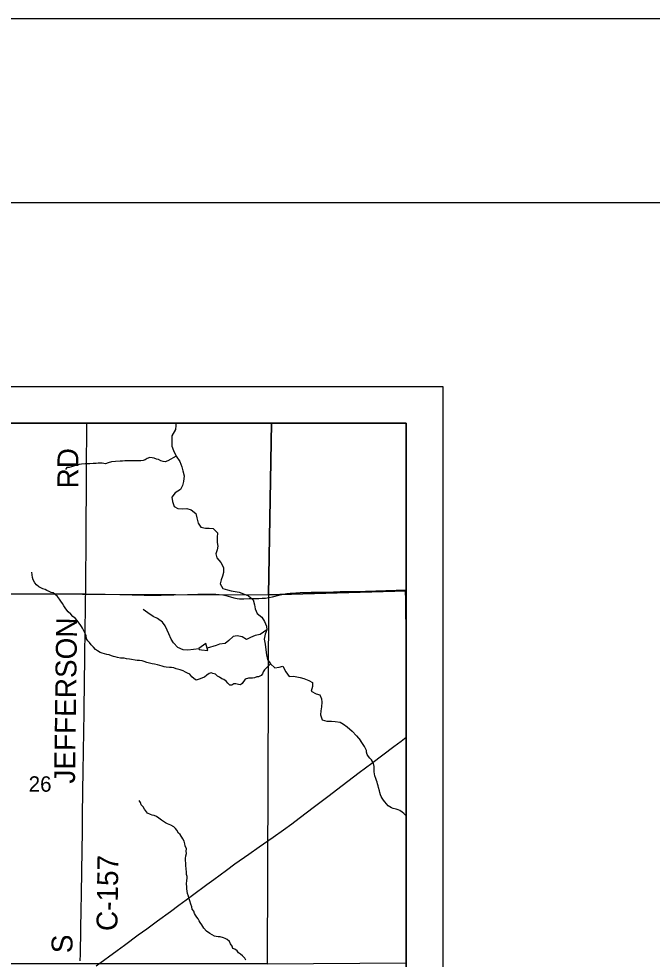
# Model space of a CAD drawing. Extents: x 0 to 34, y 0 to 22.
# Drawn here: x 7.847 to 9.569, y 19.442 to 22 of the extents above; entities that cross this region are included whole.
import ezdxf

# ---------------------------------------------------------------- set-up
doc = ezdxf.new("R2010")
doc.units = 0
for name, color, linetype in [('Default', 7, 'Continuous'), ('GM_X_County_Road', 7, 'Continuous'), ('GM_X_County_Road_Text', 7, 'Continuous'), ('GM_X_Minor_Lake', 7, 'Continuous'), ('GM_X_Minor_River', 7, 'Continuous'), ('GM_X_Section', 7, 'Continuous'), ('GM_X_Section_Text', 7, 'Continuous'), ('GM_X_State_Route', 7, 'Continuous'), ('GM_X_Township_Road', 7, 'Continuous'), ('SH_Border', 7, 'Continuous'), ('SH_Cut_Line', 7, 'Continuous'), ('SH_Data', 7, 'Continuous')]:
    doc.layers.add(name, color=color, linetype=linetype)

msp = doc.modelspace()

# ---------------------------------------------------------------- linework, layer by layer
at = {"layer": 'Default'}
msp.add_lwpolyline([(6.4755, 18.4174), (6.6827, 18.4182), (7.4947, 18.4149), (8.508, 18.4199), (8.7888, 18.4255), (8.8212, 18.4259), (8.9, 18.4271), (8.9, 20.9), (2.6032, 20.9)], dxfattribs=at)
for points in [[(8.5341, 20.9), (7.5179, 20.9), (7.5127, 20.4367), (8.5257, 20.4329)], [(8.9, 20.4436), (8.9, 20.9), (8.5341, 20.9), (8.5257, 20.4329)], [(8.9, 19.4325), (8.9, 20.4436), (8.5257, 20.4329), (8.5218, 19.4295)]]:
    msp.add_lwpolyline(points, close=True, dxfattribs=at)
at = {"layer": 'GM_X_County_Road'}
for points in [[(8.029, 20.4358), (8.0288, 20.4392), (8.029, 20.4609), (8.0294, 20.5044), (8.03, 20.5448), (8.03, 20.5635), (8.0302, 20.6132), (8.0304, 20.6505), (8.0307, 20.697), (8.0311, 20.7685), (8.0312, 20.7903), (8.0314, 20.8182), (8.0316, 20.8493), (8.032, 20.899), (8.0321, 20.9)], [(8.0142, 19.4373), (8.0145, 19.4559), (8.0151, 19.4817), (8.0153, 19.4974), (8.0156, 19.5104), (8.0159, 19.5212), (8.0159, 19.5283), (8.016, 19.5363), (8.016, 19.5444), (8.0162, 19.5564), (8.0165, 19.5698), (8.0169, 19.5912), (8.0171, 19.6037), (8.0174, 19.6254), (8.0182, 19.6751), (8.0192, 19.7435), (8.0197, 19.7839), (8.0204, 19.8304), (8.0214, 19.9019), (8.0223, 19.9516), (8.0232, 20.0075), (8.0237, 20.0603), (8.0245, 20.1131), (8.0256, 20.2032), (8.0262, 20.2529), (8.0265, 20.2685), (8.0268, 20.2933), (8.0271, 20.3119), (8.0275, 20.3492), (8.0281, 20.3865), (8.0284, 20.4051), (8.0287, 20.4268), (8.029, 20.4358)]]:
    msp.add_lwpolyline(points, dxfattribs=at)
at = {"layer": 'GM_X_Minor_Lake'}
for points in [[(8.3555, 20.3004), (8.3367, 20.2874), (8.3378, 20.2844), (8.3439, 20.2833), (8.3613, 20.2819)], [(8.3613, 20.2819), (8.3555, 20.3004)]]:
    msp.add_lwpolyline(points, dxfattribs=at)
at = {"layer": 'GM_X_Minor_River'}
for points in [[(8.2735, 20.9), (8.2742, 20.8939), (8.2728, 20.8829), (8.263, 20.8658), (8.2627, 20.8521), (8.2632, 20.8374), (8.2674, 20.8256), (8.2751, 20.8105), (8.2846, 20.7958), (8.2904, 20.781), (8.2931, 20.7708), (8.2962, 20.7568), (8.2952, 20.7416)], [(8.2751, 20.8105), (8.2519, 20.7972), (8.2451, 20.7953), (8.2391, 20.796), (8.233, 20.7979), (8.2265, 20.8009), (8.2216, 20.802), (8.2151, 20.8047), (8.2098, 20.8062), (8.2033, 20.8069), (8.1961, 20.8038), (8.1901, 20.8), (8.1848, 20.7985), (8.1791, 20.798), (8.1658, 20.7976), (8.1582, 20.7976), (8.1533, 20.7975), (8.1468, 20.7979), (8.1415, 20.7979), (8.1351, 20.7975), (8.1286, 20.7967), (8.1222, 20.7963), (8.11, 20.7958), (8.0994, 20.795), (8.0903, 20.7919), (8.0827, 20.7896), (8.074, 20.7911), (8.063, 20.7911), (8.0569, 20.7906), (8.0493, 20.7902), (8.0398, 20.7894), (8.0277, 20.7894), (8.0175, 20.7886), (8.0114, 20.7874), (8.0065, 20.7862), (8.0008, 20.7851), (7.9955, 20.7831), (7.9898, 20.7812), (7.9841, 20.7797), (7.978, 20.7793), (7.9743, 20.7739)], [(8.2952, 20.7416), (8.2918, 20.7302), (8.2862, 20.7199), (8.2722, 20.7103), (8.2628, 20.6985), (8.2644, 20.6868), (8.2698, 20.6735), (8.2793, 20.6679), (8.2918, 20.6672), (8.3039, 20.6684), (8.3153, 20.6647), (8.3282, 20.6542), (8.3313, 20.6424), (8.3344, 20.628), (8.342, 20.6171), (8.3546, 20.6145), (8.3648, 20.6149), (8.375, 20.6138), (8.3872, 20.6014), (8.3865, 20.5893), (8.3866, 20.5752), (8.3882, 20.5654), (8.3859, 20.5555), (8.3826, 20.5445), (8.3853, 20.5339), (8.396, 20.5214), (8.4036, 20.5078), (8.4033, 20.4938), (8.4007, 20.4839), (8.397, 20.4736), (8.394, 20.463), (8.402, 20.4505), (8.4146, 20.4464), (8.4248, 20.4442), (8.4354, 20.442), (8.4457, 20.4402), (8.4582, 20.4357), (8.4718, 20.4308), (8.484, 20.4199), (8.4879, 20.4055), (8.4898, 20.3949), (8.4948, 20.3828), (8.5081, 20.3726), (8.5154, 20.3609), (8.5208, 20.3477), (8.5212, 20.3378), (8.5171, 20.3264), (8.5142, 20.3127), (8.5165, 20.2991), (8.5189, 20.2836), (8.5201, 20.2703), (8.5232, 20.2574), (8.5312, 20.2453), (8.543, 20.2344), (8.5547, 20.2367), (8.5646, 20.2387), (8.573, 20.224), (8.5818, 20.2107), (8.5942, 20.2116), (8.6117, 20.2079), (8.6216, 20.2053), (8.6352, 20.2004), (8.6451, 20.1948), (8.6452, 20.1838), (8.6422, 20.1709), (8.6555, 20.1638), (8.6653, 20.1615), (8.6703, 20.1506), (8.6708, 20.1411), (8.6701, 20.1282), (8.6682, 20.1172), (8.6675, 20.1066), (8.6714, 20.0933), (8.6847, 20.0892), (8.6976, 20.0897), (8.707, 20.089), (8.7203, 20.0871), (8.7298, 20.0815), (8.7401, 20.0744), (8.7534, 20.0627), (8.7652, 20.0495), (8.7764, 20.0373)], [(7.9579, 20.4218), (7.9522, 20.429), (7.9461, 20.4339), (7.94, 20.4384), (7.935, 20.4399), (7.9297, 20.4425), (7.9236, 20.4448), (7.9187, 20.4474), (7.9122, 20.4497), (7.9073, 20.452), (7.9016, 20.455), (7.8955, 20.4603), (7.8905, 20.4656), (7.8863, 20.4735), (7.8844, 20.4807), (7.8828, 20.4952)], [(8.5312, 20.2453), (8.5149, 20.2289), (8.5115, 20.2239), (8.5092, 20.2186), (8.5062, 20.2133), (8.4987, 20.2098), (8.4937, 20.2102), (8.4881, 20.2071), (8.4824, 20.2063), (8.4771, 20.2063), (8.4714, 20.2066), (8.4626, 20.2036), (8.4544, 20.1921), (8.4494, 20.1887), (8.4441, 20.1894), (8.4369, 20.1913), (8.4312, 20.1909), (8.4263, 20.1878), (8.4206, 20.1878), (8.4156, 20.1931), (8.4111, 20.198), (8.4042, 20.2025), (8.3989, 20.2048), (8.3928, 20.2093), (8.3871, 20.2123), (8.3814, 20.2169), (8.3749, 20.2195), (8.37, 20.2206), (8.3643, 20.2195), (8.3579, 20.2145), (8.3518, 20.2091), (8.3461, 20.2072), (8.3404, 20.2045), (8.3348, 20.203), (8.3291, 20.201), (8.3226, 20.2052), (8.3173, 20.2105), (8.3119, 20.2169), (8.3058, 20.2203), (8.3001, 20.2226), (8.294, 20.226), (8.2857, 20.2294), (8.2746, 20.232), (8.2686, 20.2342), (8.2617, 20.2353), (8.2564, 20.2357), (8.2473, 20.2364), (8.242, 20.2371), (8.237, 20.239), (8.2306, 20.2413), (8.2241, 20.2424), (8.2158, 20.2442), (8.2093, 20.2457), (8.2021, 20.2476), (8.1952, 20.2495), (8.188, 20.2517), (8.1827, 20.2532), (8.1755, 20.2543), (8.1686, 20.2547), (8.1637, 20.255), (8.1538, 20.2573), (8.1478, 20.258), (8.1402, 20.2595), (8.1337, 20.2606), (8.1284, 20.261), (8.1235, 20.2613), (8.1155, 20.2628), (8.109, 20.2643), (8.1041, 20.2654), (8.0988, 20.2669), (8.0923, 20.2699), (8.0866, 20.271), (8.0797, 20.2729), (8.0737, 20.2748), (8.068, 20.2766), (8.0611, 20.2808), (8.0554, 20.2842), (8.0497, 20.291), (8.0439, 20.2971), (8.039, 20.3031), (8.0348, 20.3081), (8.0313, 20.3137), (8.0298, 20.3213), (8.0279, 20.3263), (8.0252, 20.3312), (8.0232, 20.3373), (8.0206, 20.3422), (8.0175, 20.3471), (8.0137, 20.3524), (8.0099, 20.3574), (8.006, 20.3631), (8.0003, 20.3695), (7.9942, 20.3744), (7.9881, 20.3801), (7.9812, 20.3865), (7.9778, 20.3914), (7.9732, 20.3975), (7.969, 20.4036), (7.9656, 20.4093), (7.961, 20.4157), (7.9579, 20.4218)], [(8.3371, 20.2863), (8.3064, 20.2827), (8.2939, 20.2838), (8.2795, 20.2897), (8.2677, 20.3022), (8.2612, 20.3128), (8.2546, 20.3268), (8.25, 20.3374), (8.2447, 20.3487), (8.2374, 20.3589), (8.2241, 20.3687), (8.212, 20.3743), (8.1979, 20.3845), (8.1853, 20.3935)], [(8.5212, 20.3378), (8.5031, 20.3248), (8.4899, 20.3225), (8.477, 20.3171), (8.4664, 20.3117), (8.4543, 20.3185), (8.4403, 20.3218), (8.43, 20.3195), (8.4176, 20.3088), (8.4078, 20.3011), (8.393, 20.2988), (8.3832, 20.2953), (8.3593, 20.2883)], [(8.9, 19.8321), (8.8996, 19.8325), (8.8939, 19.8386), (8.8889, 19.842), (8.8832, 19.8466), (8.8782, 19.8481), (8.8729, 19.8497), (8.8645, 19.8523), (8.8599, 19.8542), (8.8515, 19.8596), (8.8465, 19.8649), (8.8419, 19.8698), (8.8388, 19.8748), (8.8346, 19.8801), (8.832, 19.8847), (8.83, 19.8892), (8.8285, 19.8957), (8.8273, 19.9003), (8.8246, 19.909), (8.8239, 19.9136), (8.8223, 19.9193), (8.8216, 19.9238), (8.8196, 19.9284), (8.8173, 19.9334), (8.8154, 19.941), (8.8131, 19.9516), (8.8131, 19.9664), (8.8111, 19.9744), (8.8085, 19.9794), (8.8061, 19.9847), (8.8012, 19.9889), (8.7977, 19.9938), (8.7939, 19.9991), (8.7927, 20.0052), (8.792, 20.0098), (8.79, 20.0151), (8.787, 20.0208), (8.7764, 20.0373)], [(8.464, 19.4392), (8.4613, 19.4449), (8.4556, 19.451), (8.4494, 19.4559), (8.4441, 19.4594), (8.4406, 19.4647), (8.4341, 19.4689), (8.4288, 19.4715), (8.4269, 19.4772), (8.423, 19.4837), (8.4196, 19.4906), (8.4135, 19.4955), (8.4081, 19.4986), (8.4032, 19.5001), (8.3947, 19.5024), (8.3894, 19.5031), (8.3837, 19.5039), (8.3787, 19.5047), (8.3726, 19.5085), (8.3661, 19.5123), (8.3573, 19.5184), (8.35, 19.5263), (8.3447, 19.5359), (8.3397, 19.5416), (8.337, 19.5465), (8.3347, 19.5515), (8.3313, 19.5564), (8.3278, 19.5617), (8.3251, 19.5667), (8.3225, 19.5728), (8.3186, 19.5785), (8.3171, 19.5845), (8.3148, 19.5914), (8.3121, 19.6005), (8.3094, 19.6085), (8.3086, 19.6138), (8.3059, 19.6207), (8.3044, 19.6275), (8.304, 19.6336), (8.3036, 19.6389), (8.3032, 19.6469), (8.3039, 19.656), (8.3043, 19.6621), (8.3043, 19.6671), (8.3028, 19.6728), (8.3027, 19.6777), (8.3016, 19.6891), (8.3012, 19.6956), (8.3012, 19.704), (8.3004, 19.7097), (8.3004, 19.7157), (8.3015, 19.723), (8.303, 19.7291), (8.3022, 19.7363), (8.3026, 19.742), (8.2995, 19.7507), (8.2984, 19.7557), (8.2968, 19.7629), (8.293, 19.7694), (8.2861, 19.7808), (8.2811, 19.7846), (8.2765, 19.7926), (8.2727, 19.7975), (8.2689, 19.8025), (8.2601, 19.807), (8.2513, 19.8105), (8.2459, 19.8131), (8.2402, 19.8169), (8.2349, 19.8204), (8.228, 19.8253), (8.2215, 19.8299), (8.215, 19.8329), (8.21, 19.8337), (8.2047, 19.8352), (8.197, 19.8394), (8.1886, 19.85), (8.1848, 19.8561), (8.1798, 19.8622), (8.1775, 19.8679), (8.174, 19.874)]]:
    msp.add_lwpolyline(points, dxfattribs=at)
at = {"layer": 'GM_X_Section'}
msp.add_lwpolyline([(7.5127, 20.4367), (8.5257, 20.4329), (8.5218, 19.4295), (7.5091, 19.4296)], close=True, dxfattribs=at)
at = {"layer": 'GM_X_State_Route'}
msp.add_lwpolyline([(8.0571, 19.4236), (8.1141, 19.4657), (8.1341, 19.4806), (8.1715, 19.5081), (8.1948, 19.5245), (8.2243, 19.5467), (8.259, 19.5719), (8.2823, 19.5889), (8.3016, 19.6033), (8.3189, 19.616), (8.3586, 19.6452), (8.3769, 19.6587), (8.4113, 19.6842), (8.4346, 19.7011), (8.4728, 19.7281), (8.5001, 19.7473), (8.5387, 19.7744), (8.5668, 19.7942), (8.5896, 19.8104), (8.6095, 19.8252), (8.6512, 19.8573), (8.6904, 19.8872), (8.7103, 19.9025), (8.742, 19.9265), (8.7724, 19.9495), (8.8067, 19.9755), (8.8364, 19.9982), (8.8666, 20.0207), (8.8864, 20.0355), (8.9, 20.0457)], dxfattribs=at)
at = {"layer": 'GM_X_Township_Road'}
msp.add_line((8.8984, 20.4466), (8.9, 20.4466), dxfattribs=at)
for points in [[(8.029, 20.4358), (8.0817, 20.4345), (8.1221, 20.4336), (8.1874, 20.4326), (8.2091, 20.4324), (8.234, 20.4323), (8.2681, 20.4331), (8.3054, 20.4337), (8.3333, 20.4345), (8.3643, 20.435), (8.3829, 20.4349), (8.3921, 20.4343), (8.4013, 20.433), (8.4103, 20.4309), (8.4221, 20.4275), (8.4312, 20.425), (8.4404, 20.4232), (8.4466, 20.4224), (8.4529, 20.4221), (8.4591, 20.4221), (8.4737, 20.4228), (8.487, 20.4231), (8.4994, 20.4233), (8.5087, 20.4237), (8.5179, 20.4245), (8.5271, 20.4258), (8.5363, 20.4277), (8.5573, 20.4333), (8.5662, 20.4354), (8.5753, 20.437), (8.5845, 20.4379), (8.6, 20.4388), (8.6124, 20.4392), (8.6418, 20.44), (8.6639, 20.4405), (8.7028, 20.4415), (8.721, 20.4418), (8.7521, 20.4423), (8.7893, 20.4431), (8.8452, 20.4449), (8.8731, 20.4457), (8.8984, 20.4466)], [(8.9, 20.3634), (8.9, 20.3637), (8.8996, 20.3698), (8.8995, 20.3821), (8.8991, 20.416), (8.8984, 20.4466)], [(7.5169, 20.4363), (7.5536, 20.436), (7.6002, 20.4357), (7.6375, 20.4359), (7.6779, 20.4358), (7.7307, 20.4358), (7.7649, 20.4359), (7.8115, 20.4361), (7.8426, 20.4362), (7.883, 20.4363), (7.9172, 20.4362), (7.942, 20.4362), (7.9637, 20.4362), (7.9824, 20.4361), (8.0103, 20.4359), (8.029, 20.4358)]]:
    msp.add_lwpolyline(points, dxfattribs=at)
at = {"layer": 'SH_Border'}
msp.add_lwpolyline([(1.5, 21.5), (33.5, 21.5), (33.5, 0.5), (1.5, 0.5)], close=True, dxfattribs=at)
at = {"layer": 'SH_Cut_Line'}
msp.add_lwpolyline([(0, 0), (34, 0), (34, 22), (0, 22)], close=True, dxfattribs=at)
msp.add_lwpolyline([(8.9, 14.3696), (8.9, 20.9), (2.6032, 20.9)], dxfattribs=at)
at = {"layer": 'SH_Data'}
for p, q in [((2, 21), (9, 21)), ((9, 21), (9, 14)), ((2.1, 20.9), (8.9, 20.9)), ((8.9, 20.9), (8.9, 14.1))]:
    msp.add_line(p, q, dxfattribs=at)

# ---------------------------------------------------------------- texts
at = {"layer": 'GM_X_County_Road_Text'}
for s, height, rotation, p in [('RD', 0.05682, 90, (8.0089, 20.7225)), ('JEFFERSON', 0.05682, 89.2508, (7.9997, 19.9194)), ('C-157', 0.05682, 89.1819, (8.1149, 19.5183)), ('S', 0.0568, 90, (7.993, 19.4584))]:
    msp.add_text(s, height=height, rotation=rotation, dxfattribs=at).set_placement(p)
at = {"layer": 'GM_X_Section_Text'}
msp.add_text('26', height=0.04186, rotation=0, dxfattribs=at).set_placement((7.8737, 19.8976))

doc.saveas('drawing.dxf')
